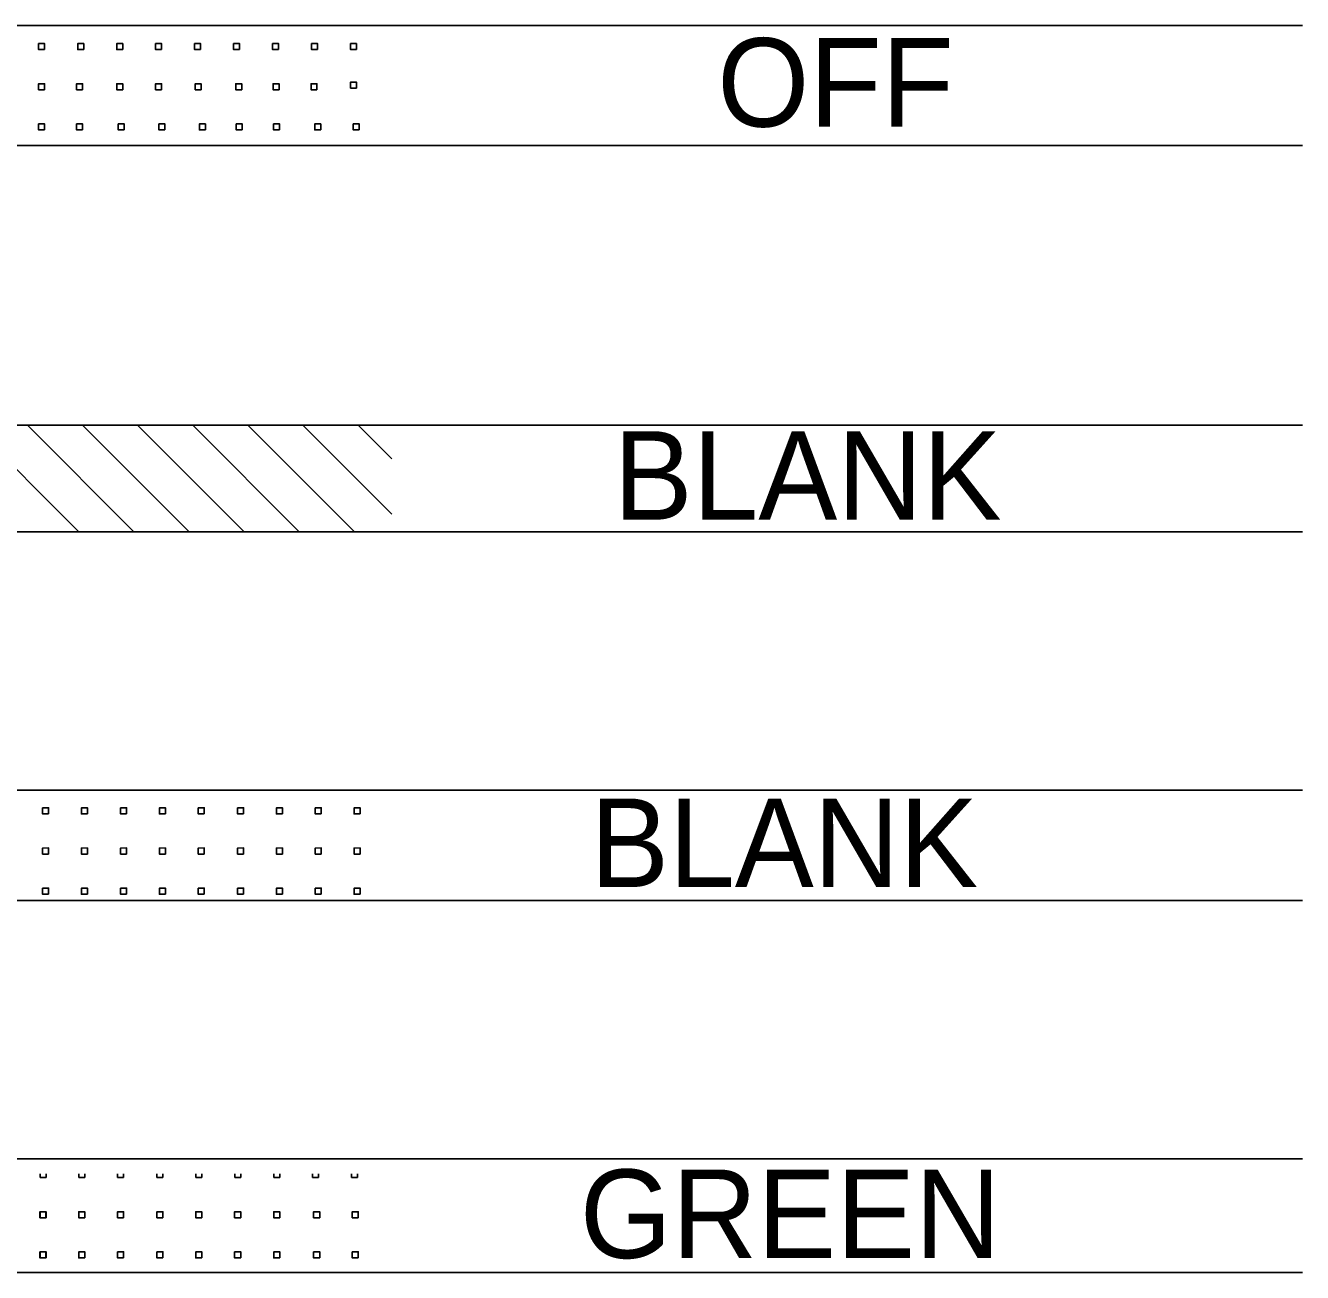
# Model space of a CAD drawing. Extents: x 15 to 764, y 7 to 487.
# Drawn here: x 706.1 to 756.6, y 134.7 to 184 of the extents above; entities that cross this region are included whole.
import ezdxf

# ---------------------------------------------------------------- set-up
doc = ezdxf.new("R2010")
doc.units = 0
doc.layers.add('Default', color=7, linetype='Continuous')
doc.layers.add('TextStructures', color=7, linetype='Continuous')

msp = doc.modelspace()

# ---------------------------------------------------------------- linework, layer by layer
at = {"layer": 'Default'}
for p, q in [((756.61, 183.984), (462.687, 183.984)), ((462.687, 179.246), (756.61, 179.246)), ((462.687, 168.178), (756.61, 168.178)), ((708.347, 168.178), (712.561, 163.965)), ((710.527, 168.178), (714.742, 163.965)), ((712.708, 168.178), (716.922, 163.965)), ((714.888, 168.178), (719.103, 163.965)), ((717.069, 168.178), (720.584, 164.664)), ((719.249, 168.178), (720.584, 166.844)), ((462.687, 163.965), (756.61, 163.965)), ((462.687, 153.744), (756.61, 153.744)), ((462.687, 149.383), (756.61, 149.383)), ((462.687, 139.163), (756.61, 139.163)), ((462.687, 134.675), (756.61, 134.675))]:
    msp.add_line(p, q, dxfattribs=at)
for points in [[(706.847, 183.03), (706.847, 183.27), (706.61, 183.269), (706.61, 183.03), (706.847, 183.03)], [(706.847, 183.03), (706.847, 183.27), (706.61, 183.269), (706.61, 183.03), (706.847, 183.03)], [(708.395, 183.03), (708.395, 183.27), (708.158, 183.269), (708.158, 183.03), (708.395, 183.03)], [(709.937, 183.03), (709.937, 183.27), (709.7, 183.269), (709.7, 183.03), (709.937, 183.03)], [(711.478, 183.03), (711.478, 183.27), (711.242, 183.269), (711.242, 183.03), (711.478, 183.03)], [(713.02, 183.03), (713.02, 183.27), (712.784, 183.269), (712.784, 183.03), (713.02, 183.03)], [(714.562, 183.03), (714.562, 183.27), (714.325, 183.269), (714.325, 183.03), (714.562, 183.03)], [(716.104, 183.03), (716.104, 183.27), (715.867, 183.269), (715.867, 183.03), (716.104, 183.03)], [(717.646, 183.03), (717.646, 183.27), (717.409, 183.269), (717.409, 183.03), (717.646, 183.03)], [(719.187, 183.03), (719.187, 183.27), (718.951, 183.269), (718.951, 183.03), (719.187, 183.03)], [(706.847, 181.443), (706.847, 181.683), (706.61, 181.682), (706.61, 181.443), (706.847, 181.443)], [(706.847, 181.443), (706.847, 181.683), (706.61, 181.682), (706.61, 181.443), (706.847, 181.443)], [(708.352, 181.443), (708.352, 181.683), (708.115, 181.682), (708.115, 181.443), (708.352, 181.443)], [(709.937, 181.443), (709.937, 181.683), (709.7, 181.682), (709.7, 181.443), (709.937, 181.443)], [(711.478, 181.443), (711.478, 181.683), (711.242, 181.682), (711.242, 181.443), (711.478, 181.443)], [(713.042, 181.443), (713.042, 181.683), (712.805, 181.682), (712.805, 181.443), (713.042, 181.443)], [(714.648, 181.443), (714.648, 181.683), (714.411, 181.682), (714.411, 181.443), (714.648, 181.443)], [(716.125, 181.443), (716.125, 181.683), (715.889, 181.682), (715.889, 181.443), (716.125, 181.443)], [(717.624, 181.443), (717.624, 181.683), (717.388, 181.682), (717.388, 181.443), (717.624, 181.443)], [(719.187, 181.51), (719.187, 181.75), (718.951, 181.749), (718.951, 181.51), (719.187, 181.51)], [(706.847, 179.854), (706.847, 180.094), (706.61, 180.093), (706.61, 179.854), (706.847, 179.854)], [(706.847, 179.854), (706.847, 180.094), (706.61, 180.093), (706.61, 179.854), (706.847, 179.854)], [(708.352, 179.854), (708.352, 180.094), (708.115, 180.093), (708.115, 179.854), (708.352, 179.854)], [(710.001, 179.854), (710.001, 180.094), (709.764, 180.093), (709.764, 179.854), (710.001, 179.854)], [(711.607, 179.854), (711.607, 180.094), (711.37, 180.093), (711.37, 179.854), (711.607, 179.854)], [(713.213, 179.854), (713.213, 180.094), (712.976, 180.093), (712.976, 179.854), (713.213, 179.854)], [(714.669, 179.854), (714.669, 180.094), (714.432, 180.093), (714.432, 179.854), (714.669, 179.854)], [(716.147, 179.854), (716.147, 180.094), (715.91, 180.093), (715.91, 179.854), (716.147, 179.854)], [(717.774, 179.854), (717.774, 180.094), (717.537, 180.093), (717.537, 179.854), (717.774, 179.854)], [(719.295, 179.854), (719.295, 180.094), (719.058, 180.093), (719.058, 179.854), (719.295, 179.854)], [(703.987, 168.178), (708.201, 163.965)], [(706.167, 168.178), (710.381, 163.965)], [(708.346, 168.178), (708.376, 168.148)], [(707.003, 152.809), (707.003, 153.049), (706.767, 153.046), (706.767, 152.809), (707.003, 152.809)], [(707.003, 152.809), (707.003, 153.049), (706.767, 153.046), (706.767, 152.809), (707.003, 152.809)], [(708.539, 152.809), (708.539, 153.049), (708.303, 153.046), (708.303, 152.809), (708.539, 152.809)], [(708.376, 153.046), (708.354, 153.046)], [(710.093, 152.809), (710.093, 153.049), (709.856, 153.046), (709.856, 152.809), (710.093, 152.809)], [(711.629, 152.809), (711.629, 153.049), (711.392, 153.046), (711.392, 152.809), (711.629, 152.809)], [(713.165, 152.809), (713.165, 153.049), (712.928, 153.046), (712.928, 152.809), (713.165, 152.809)], [(714.718, 152.809), (714.718, 153.049), (714.482, 153.046), (714.482, 152.809), (714.718, 152.809)], [(716.254, 152.809), (716.254, 153.049), (716.018, 153.046), (716.018, 152.809), (716.254, 152.809)], [(717.79, 152.809), (717.79, 153.049), (717.554, 153.046), (717.554, 152.809), (717.79, 152.809)], [(719.326, 152.809), (719.326, 153.049), (719.089, 153.046), (719.089, 152.809), (719.326, 152.809)], [(707.003, 151.221), (707.003, 151.46), (706.767, 151.459), (706.767, 151.221), (707.003, 151.221)], [(707.003, 151.221), (707.003, 151.46), (706.767, 151.459), (706.767, 151.221), (707.003, 151.221)], [(708.539, 151.221), (708.539, 151.46), (708.303, 151.459), (708.303, 151.221), (708.539, 151.221)], [(710.093, 151.221), (710.093, 151.46), (709.856, 151.459), (709.856, 151.221), (710.093, 151.221)], [(711.629, 151.221), (711.629, 151.46), (711.392, 151.459), (711.392, 151.221), (711.629, 151.221)], [(713.165, 151.221), (713.165, 151.46), (712.928, 151.459), (712.928, 151.221), (713.165, 151.221)], [(714.718, 151.221), (714.718, 151.46), (714.482, 151.459), (714.482, 151.221), (714.718, 151.221)], [(716.254, 151.221), (716.254, 151.46), (716.018, 151.459), (716.018, 151.221), (716.254, 151.221)], [(717.79, 151.221), (717.79, 151.46), (717.554, 151.459), (717.554, 151.221), (717.79, 151.221)], [(719.326, 151.221), (719.326, 151.46), (719.089, 151.459), (719.089, 151.221), (719.326, 151.221)], [(707.003, 149.632), (707.003, 149.873), (706.767, 149.87), (706.767, 149.632), (707.003, 149.632)], [(707.003, 149.632), (707.003, 149.873), (706.767, 149.87), (706.767, 149.632), (707.003, 149.632)], [(708.539, 149.632), (708.539, 149.873), (708.303, 149.87), (708.303, 149.632), (708.539, 149.632)], [(710.093, 149.632), (710.093, 149.873), (709.856, 149.87), (709.856, 149.632), (710.093, 149.632)], [(711.629, 149.632), (711.629, 149.873), (711.392, 149.87), (711.392, 149.632), (711.629, 149.632)], [(713.165, 149.632), (713.165, 149.873), (712.928, 149.87), (712.928, 149.632), (713.165, 149.632)], [(714.718, 149.632), (714.718, 149.873), (714.482, 149.87), (714.482, 149.632), (714.718, 149.632)], [(716.254, 149.632), (716.254, 149.873), (716.018, 149.87), (716.018, 149.632), (716.254, 149.632)], [(717.79, 149.632), (717.79, 149.873), (717.554, 149.87), (717.554, 149.632), (717.79, 149.632)], [(719.326, 149.632), (719.326, 149.873), (719.089, 149.87), (719.089, 149.632), (719.326, 149.632)], [(706.672, 138.571), (706.672, 138.428)], [(706.672, 138.428), (706.908, 138.428)], [(706.908, 138.428), (706.908, 138.571)], [(708.199, 138.571), (708.199, 138.428)], [(708.199, 138.428), (708.435, 138.428)], [(708.435, 138.428), (708.435, 138.571)], [(709.738, 138.571), (709.738, 138.428)], [(709.738, 138.428), (709.975, 138.428)], [(709.975, 138.428), (709.975, 138.571)], [(711.29, 138.571), (711.29, 138.428)], [(711.29, 138.428), (711.526, 138.428)], [(711.526, 138.428), (711.526, 138.571)], [(712.829, 138.571), (712.829, 138.428)], [(712.829, 138.428), (713.066, 138.428)], [(713.066, 138.428), (713.066, 138.571)], [(714.368, 138.571), (714.368, 138.428)], [(714.368, 138.428), (714.605, 138.428)], [(714.605, 138.428), (714.605, 138.571)], [(715.914, 138.571), (715.914, 138.428)], [(715.914, 138.428), (716.151, 138.428)], [(716.151, 138.428), (716.151, 138.571)], [(717.453, 138.571), (717.453, 138.428)], [(717.453, 138.428), (717.69, 138.428)], [(717.69, 138.428), (717.69, 138.571)], [(718.993, 138.571), (718.993, 138.428)], [(718.993, 138.428), (719.229, 138.428)], [(719.229, 138.428), (719.229, 138.571)], [(706.9, 136.838), (706.9, 137.077), (706.661, 137.076), (706.661, 136.838), (706.9, 136.838)], [(706.91, 136.838), (706.91, 137.077), (706.671, 137.076), (706.671, 136.838), (706.91, 136.838)], [(708.436, 136.838), (708.436, 137.077), (708.197, 137.076), (708.197, 136.838), (708.436, 136.838)], [(709.976, 136.838), (709.976, 137.077), (709.737, 137.076), (709.737, 136.838), (709.976, 136.838)], [(711.528, 136.838), (711.528, 137.077), (711.289, 137.076), (711.289, 136.838), (711.528, 136.838)], [(713.067, 136.838), (713.067, 137.077), (712.828, 137.076), (712.828, 136.838), (713.067, 136.838)], [(714.606, 136.838), (714.606, 137.077), (714.367, 137.076), (714.367, 136.838), (714.606, 136.838)], [(716.152, 136.838), (716.152, 137.077), (715.913, 137.076), (715.913, 136.838), (716.152, 136.838)], [(717.731, 136.838), (717.731, 137.077), (717.492, 137.076), (717.492, 136.838), (717.731, 136.838)], [(719.257, 136.838), (719.257, 137.077), (719.019, 137.076), (719.019, 136.838), (719.257, 136.838)], [(706.9, 135.25), (706.9, 135.49), (706.661, 135.488), (706.661, 135.25), (706.9, 135.25)], [(706.91, 135.25), (706.91, 135.49), (706.671, 135.488), (706.671, 135.25), (706.91, 135.25)], [(708.436, 135.25), (708.436, 135.49), (708.197, 135.488), (708.197, 135.25), (708.436, 135.25)], [(709.976, 135.25), (709.976, 135.49), (709.737, 135.488), (709.737, 135.25), (709.976, 135.25)], [(711.528, 135.25), (711.528, 135.49), (711.289, 135.488), (711.289, 135.25), (711.528, 135.25)], [(713.067, 135.25), (713.067, 135.49), (712.828, 135.488), (712.828, 135.25), (713.067, 135.25)], [(714.606, 135.25), (714.606, 135.49), (714.367, 135.488), (714.367, 135.25), (714.606, 135.25)], [(716.152, 135.25), (716.152, 135.49), (715.913, 135.488), (715.913, 135.25), (716.152, 135.25)], [(717.731, 135.25), (717.731, 135.49), (717.492, 135.488), (717.492, 135.25), (717.731, 135.25)], [(719.257, 135.25), (719.257, 135.49), (719.019, 135.488), (719.019, 135.25), (719.257, 135.25)]]:
    msp.add_lwpolyline(points, dxfattribs=at)

# ---------------------------------------------------------------- texts
at = {"layer": 'TextStructures'}
for s, p in [('OFF', (733.46, 179.986)), ('BLANK', (729.36, 164.443)), ('BLANK', (728.43, 149.916)), ('GREEN', (728.022, 135.244))]:
    msp.add_text(s, height=3.5, rotation=0.0007, dxfattribs=at).set_placement(p)

doc.saveas('drawing.dxf')
